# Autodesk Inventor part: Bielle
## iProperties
Shininess: 41.0
Length Units: 11269
Angle Units: 11279
Time Units: 11290
Mass Units: 11283
Length Display Precision: 3
Angle Display Precision: 2
Created: 2001-06
Part Number: Bielle
Material: Par défaut
Document SubType Name: Modélisation
Designer: Flavien MARTY
Density: 0.0
Volumn: 0.0
Area: 0.0
PropertySet Name: Model Information
Control State: 0
Master: False
Checked Out: False
Author: Flavien MARTY
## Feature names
1. Extrusion1
2. Extrusion2
3. Extrusion3
4. Congé1 [Fillet]
5. Perçage1 [Hole]
6. Extrusion4
7. Extrusion5
8. Extrusion6
9. Extrusion7
